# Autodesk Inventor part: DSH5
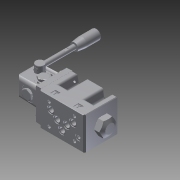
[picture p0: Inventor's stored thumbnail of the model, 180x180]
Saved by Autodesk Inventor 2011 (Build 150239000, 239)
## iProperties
Created: 2012-01
Part Number: DSH5
Document SubType Name: Modeling
Designer: khramov
Density: 1 g/cm^3
Author: khramov
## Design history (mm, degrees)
derived "DSH5_S1_20N.iam"
node "Твердое тело1"
node "0144305_.ipt:1"
node "0144431_.ipt:1"
sketch "0530295_UNI_5931___M6x18.ipt:1"
sketch "0530295_UNI_5931___M6x18.ipt:2"
sketch "0530295_UNI_5931___M6x18.ipt:3"
sketch "0530295_UNI_5931___M6x18.ipt:4"
sketch "0144429_.ipt:1"
sketch "0144429_.ipt:2"
node "0144429_.ipt:3"
sketch "0144286_.ipt:1"
sketch "0144300.ipt:1"
sketch "0630596.ipt:1"
node "0144301.ipt:1"
sketch "3001350000.ipt:1"
sketch "0530779.ipt:1"
sketch "0530779.ipt:2"
